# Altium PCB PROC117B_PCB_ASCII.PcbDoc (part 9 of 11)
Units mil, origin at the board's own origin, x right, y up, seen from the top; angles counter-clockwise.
Board outline 2480.32 x 3185.25 mil, 8 copper layers (Top Layer, L2_GND1, L3_SIG1, L4_PWR1, L5_PWR2, L6_SIG2, L7_GND2, Bottom Layer), stack 57.4 mil thick; 456 components, 292 nets, 7831 pads, 2905 vias.
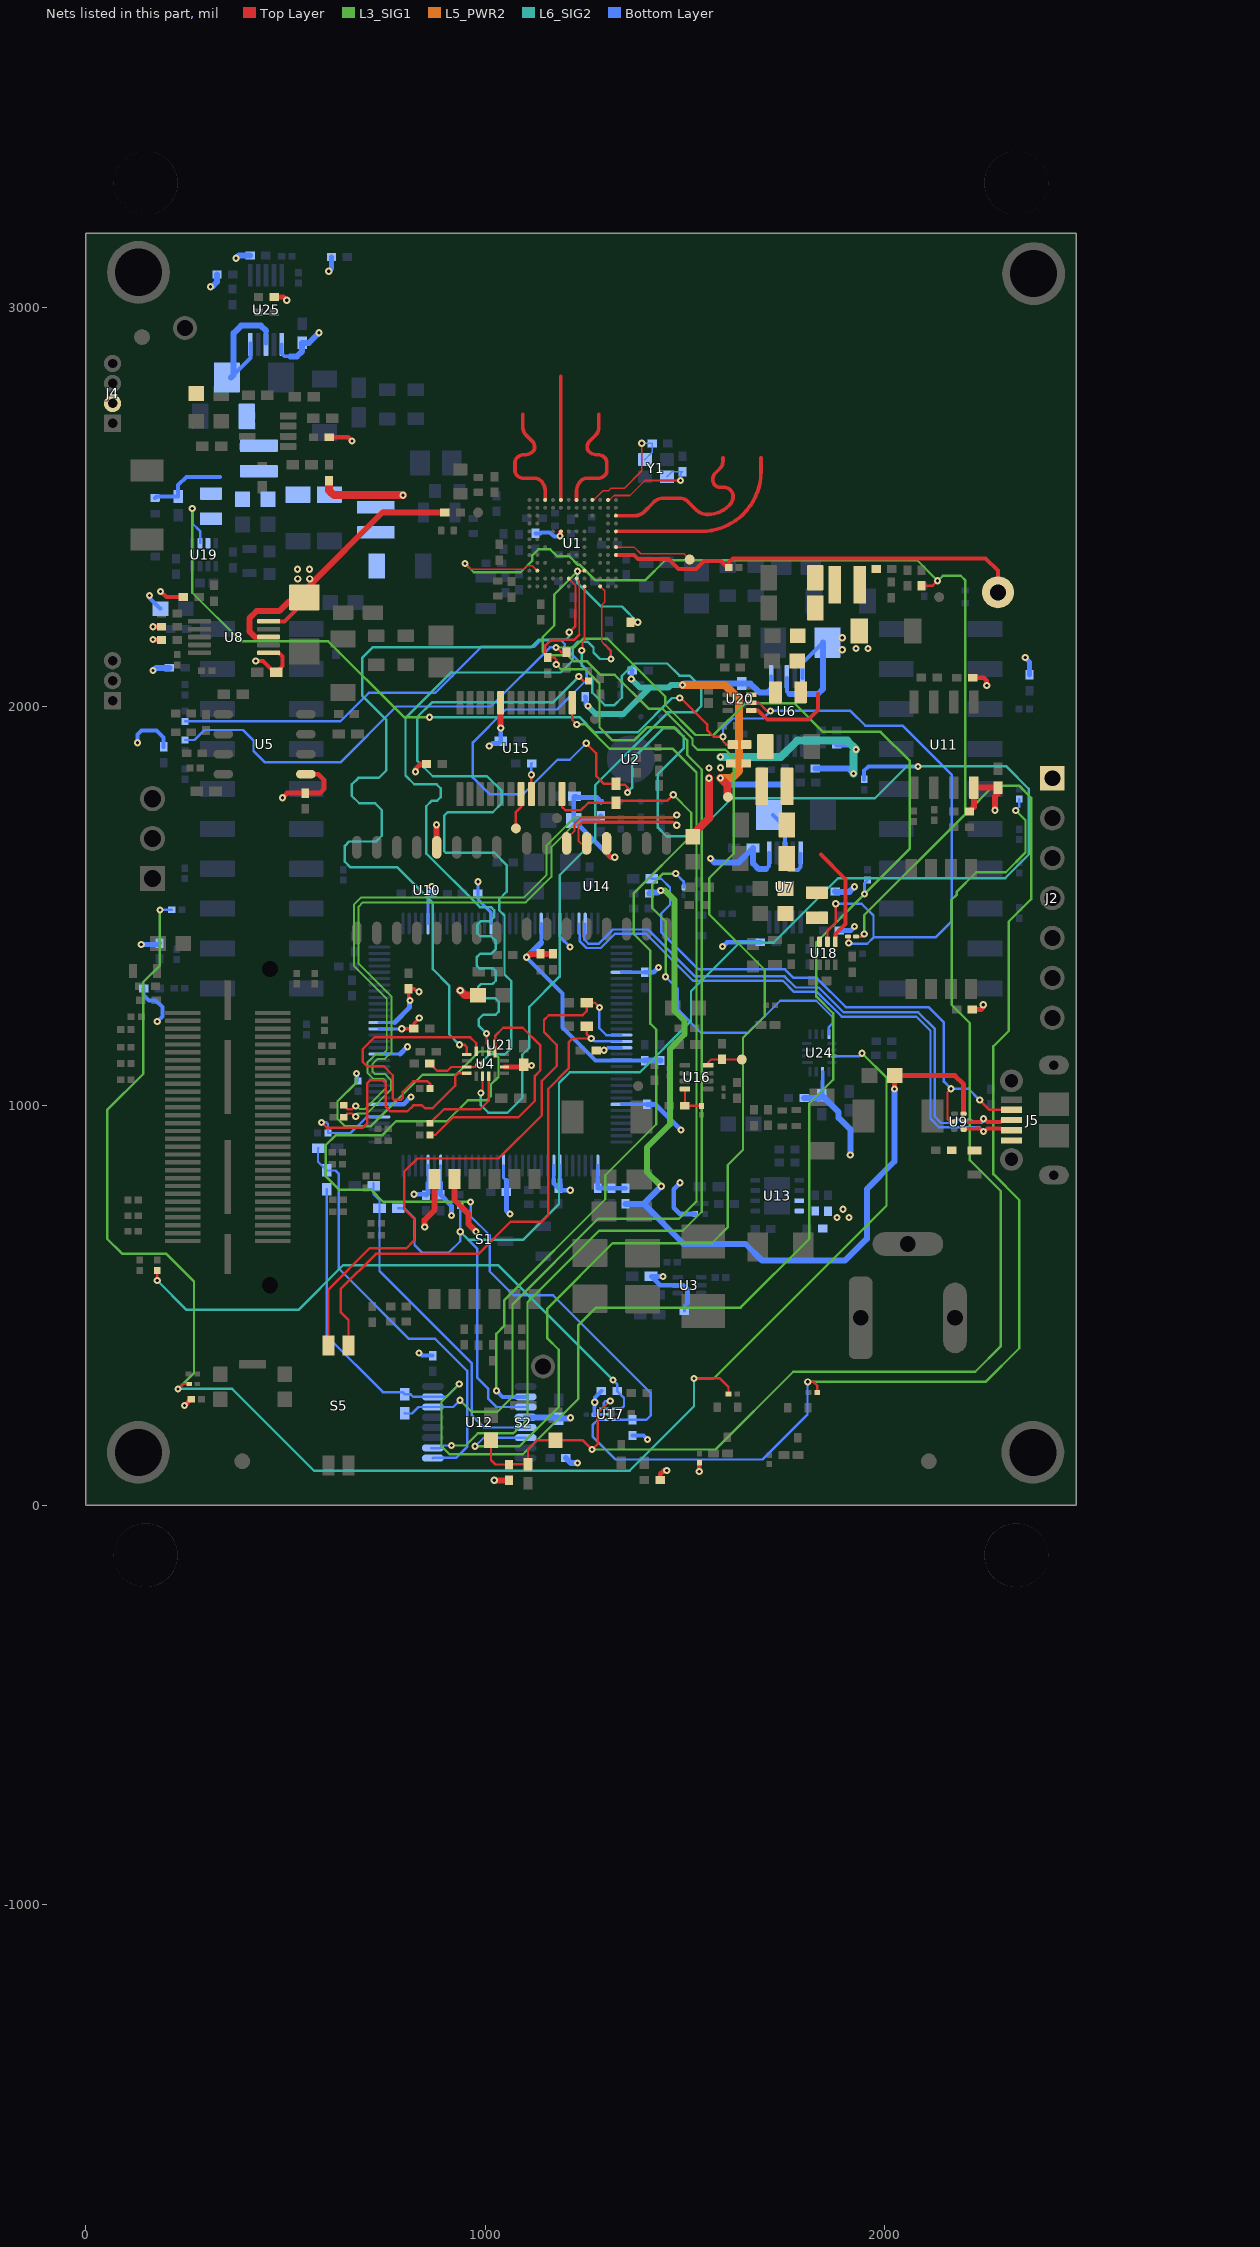
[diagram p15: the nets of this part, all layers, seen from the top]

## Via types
v1: diameter 18, hole 8, Top Layer to Bottom Layer, tented both sides, 2905 vias

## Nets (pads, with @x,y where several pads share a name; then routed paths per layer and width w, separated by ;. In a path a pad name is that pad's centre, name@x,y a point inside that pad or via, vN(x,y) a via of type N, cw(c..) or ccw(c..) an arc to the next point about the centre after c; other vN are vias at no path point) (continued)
RADAR_LVDS_FRCLKM: R220.2 U14.5 | length 1960.4
  Top Layer w5.2: R220.2@645.83,971.22 646.62,971.22 652.29,976.89 652.29,978.08 655.33,981.12 666.38,981.12 674.28,973.22 v1(675.83,973.22) ; U14.5@1254.22,1657.18 1239.83,1657.18 1234.32,1662.68 1234.32,1701.84 1243.87,1711.39 1469.39,1711.39 1478.2,1702.58 v1(1479.75,1702.58)
  L3_SIG1 w4.8: v1(675.83,973.22) 675.83,977 679.05,980.22 704.2,980.22 760.48,1036.5 763.99,1040.01 763.99,1065.29 749.75,1079.53 724.78,1079.53 717.58,1086.73 717.58,1104.64 730.6,1117.66 749.15,1117.66 765.65,1134.16 765.65,1273.65 683.17,1356.13 683.17,1498.96 693.76,1509.55 1102.17,1509.55 1165.8,1573.18 1165.8,1647.32 1228.05,1709.58 1476.23,1709.58 1479.75,1706.06 v1(1479.75,1702.58)
RADAR_LVDS_FRCLKP: R219.2 U14.6 | length 1966.3
  Top Layer w5.2: R219.2@645.83,1001.22 646.62,1001.22 652.29,995.55 652.29,994.37 655.33,991.32 666.38,991.32 674.28,999.22 v1(675.83,999.22) ; U14.6@1204.22,1657.18 1204.22,1669.04 1224.12,1688.94 1224.12,1706.07 1239.64,1721.59 1471.21,1721.59 1478.2,1728.58 v1(1479.75,1728.58)
  L3_SIG1 w4.8: v1(675.83,999.22) 678.3,999.22 685.3,992.22 699.23,992.22 751.99,1044.98 751.99,1060.32 744.78,1067.53 719.81,1067.53 705.58,1081.75 705.58,1109.61 725.63,1129.66 744.18,1129.66 753.65,1139.13 753.65,1268.68 671.17,1351.16 671.17,1503.93 688.79,1521.55 1097.2,1521.55 1153.8,1578.15 1153.8,1652.3 1223.08,1721.58 1470.28,1721.58 1477.28,1728.58 v1(1479.75,1728.58) v1@1482.22,1728.58
RADAR_NRST: R20.1 R171.1 R176.1 U1.L10 U17.4 | length 5647.1
  Top Layer w4: v1(949.71,2358.2) 964.56,2343.34 1061.19,2343.34 1096.59,2343.46 1105.56,2352.43 1118.35,2352.43 U1.L10@1130.68,2340.09
  Top Layer w6: v1(1808.03,308.72) 1822.18,308.72 1832.03,298.88 R171.1@1832.03,281.86 ; R176.1@1928.78,1423.59 1942.92,1423.59 1949.21,1429.88 v1(1949.27,1429.88) ; R20.1@2092.59,2302.27 2120.49,2302.27 v1(2133.25,2315.03)
  L3_SIG1 w6: v1(949.71,2358.2) 949.71,2357.89 971.5,2336.09 1045.03,2336.09 1089.09,2336.09 1118.25,2365.26 1118.25,2378.67 1133,2393.41 1162.99,2393.41 1179.98,2376.42 1210.58,2376.42 1232.3,2354.7 1237.61,2354.7 1276.52,2315.79 1400.78,2315.79 1451.15,2366.15 2082.13,2366.15 v1(2133.25,2315.03) 2134.12,2315.03 2146.41,2327.32 2190.94,2327.32 2202.8,2315.46 2202.8,1731.03 ; v1(1808.03,308.72) 2253.43,308.72 2337.65,392.95 2337.65,764.06 2272.88,828.83 2272.88,1149.03 2311.25,1187.4 2311.25,1461.23 2367.33,1517.31 2367.33,1771.56 2337.03,1801.86 2273.63,1801.86 2202.8,1731.03 ; v1(1949.27,1429.88) 1949.27,1477.5 2202.8,1731.03
  Bottom Layer w6: U17.4@1297.06,213.79 1282,213.79 1269.92,201.71 1269.92,170.6 1326.34,114.19 1694.32,114.19 1807.37,227.23 1807.37,308.07 v1(1808.03,308.72)
RADAR_NRST_1: R63.1 R123.1 U17.1 | length 1461.9
  Top Layer w6: R63.1@178.77,587.81 178.77,562.52 v1(178.88,562.41)
  L6_SIG2 w6: v1(178.88,562.41) 252.48,488.8 532.5,488.8 644.67,600.98 1032.64,600.98 v1(1320.06,313.56)
  Bottom Layer w6: v1(1320.06,313.56) 1330.48,303.14 R123.1@1330.48,286.13 1347.92,268.68 1347.92,247.86 1341.68,241.62 1328.98,241.62 U17.1@1328.64,241.27
RADAR_NRST_2: C53.1 R144.2 R165.1 S2.3 S2.4 U17.6 | length 3223.4
  Top Layer w6: S2.3@1014.65,162.25 1014.65,113.17 1026.18,101.64 R165.1@1059.52,101.64 1060.06,102.18 C53.1@1107.4,102.18 1107.4,140.54 1129.11,162.25 S2.4@1176.07,162.25 1245.19,162.25 v1(1268.03,139.41) 1281.95,153.32 1281.95,230.43 1312,260.48 v1(1313.49,260.48)
  L3_SIG1 w6: v1(1268.03,139.41) 1576.81,139.41 1771.53,334.13 2227.54,334.13 2291.74,398.33 2291.74,785.89 2213.63,863.99 2213.63,1207.19 2168.48,1252.34 2168.48,1516.08 2180.67,1528.26 2180.67,1535.44 2230.07,1584.83 2303.72,1584.83 2353.12,1634.23 2353.12,1715.1 2328.74,1739.48 v1(2328.74,1739.75)
  Bottom Layer w6: U17.6@1297.14,241.27 1297.14,256.35 1301.27,260.48 v1(1313.49,260.48) ; v1(2328.74,1739.75) 2337.72,1748.72 R144.2@2337.72,1768.04
RADAR_OSC_CLKOUT: TP5.1 U1.A7 | length 197.5
  Top Layer w4: U1.A7@1327.53,2399.14 1372.89,2399.14 1389.63,2382.41 1497.99,2382.41 TP5.1@1512.19,2368.21
RADAR_VBGAP: C6.1 U1.H5 | length 79.3
  Top Layer w10: v1@1187.9,2426.87 1187.98,2426.96 1187.98,2436.9 U1.H5@1189.59,2438.51
  Bottom Layer w10: C6.1@1125.93,2433.58 1138.28,2433.58 1140.85,2436.16 1161.58,2436.16 1169.56,2428.17 1170.97,2428.17 1173.85,2425.3 1185.21,2425.3 v1@1186.74,2423.77
  other v1: 1187.35,2426.87
REG_1V2: C61.2 L5.2 R86.2 R193.1 U8.8 U8.10 | length 795.3
  Top Layer w10: U8.8@454.65,2173.58 424.5,2173.58 424.61,2173.69 454.76,2173.69 U8.8@454.84,2173.77 ; U8.10@454.84,2213.14 497.82,2213.14 R193.1@547.27,2262.59
  Top Layer w15: 424.5,2173.58 409.76,2188.31 409.76,2220.8 427.63,2238.67 484.43,2238.67 508.35,2262.59 R193.1@547.27,2262.59 ; R193.1@560.88,2303.88 743.17,2486.17 R86.2@899.02,2486.17
  other v1: 530.64,2319.62 560.64,2319.62 530.18,2343.72 560.18,2343.72
REG_1V8: C68.2 L6.2 R67.2 R192.1 U6.8 U6.10 | length 358.6
  Bottom Layer w10: U6.8@1755.6,2071.89 1755.68,2071.82 1755.68,2037.44 1761.92,2031.21 ; U6.10@1794.9,2071.82 1794.97,2071.9 1794.97,2108.35 R192.1@1846.57,2159.94
  Bottom Layer w15: 1761.92,2031.21 1833.56,2031.21 1846.57,2044.22 R192.1@1846.57,2159.94
  other v1: 1894.25,2142.27 1928.89,2145.49 1958.89,2145.49 1894.25,2172.27
REG_3V3: C54.2 L4.2 L11.1 R175.2
REG_MODE_SELECT: R173.2 U24.8 | length 962.2
  L3_SIG1 w6: v1(1451.98,1323.34) 1451.98,1462.11 1418.4,1495.69 1418.4,1554.61 1445.3,1581.52 v1(1477.34,1581.52)
  Bottom Layer w6: v1(1451.98,1323.34) 1482.75,1292.57 1482.75,1240.95 1540.68,1183.02 1658.67,1183.02 1738.92,1263.26 1829.29,1263.26 1870.7,1221.85 1870.7,1206.94 1860.85,1197.09 U24.8@1860.85,1179.47 ; v1(1477.34,1581.52) 1496.97,1561.88 R173.2@1496.97,1546.64
REG_OUT_1V2: C100.1 C119.1 C120.1 C121.2 C122.2 L1.1 L5.1 L14.2 R119.2 | length 200.9
  Bottom Layer w10: R119.2@173.4,2521.99 177.34,2525.92 C100.1@231.43,2525.92 231.43,2554.55 251.9,2575.02 335.59,2575.02
REG_OUT_1V8: C128.1 C129.1 C130.2 C131.2 L6.1 L15.2 U20.5 | length 227.8
  Top Layer w10: U20.5@1666.44,1989.74 1683.73,1989.74 1706.56,1966.91 1809.81,1966.91 1833.91,1991.01 1833.91,2031.87
REG_OUT_3V3: C70.1 C71.1 C87.2 C107.2 L4.1 L13.2 U18.5 | length 253.4
  Top Layer w10: 1840.73,1628.74 1902.12,1567.35 1902.12,1454.84 1877,1429.72 U18.5@1877,1411.2
REG_PG: R175.1 R176.2 U18.6 U19.6 U20.6 | length 3569.1
  Top Layer w6: v1@1487.69,2021.63 1489.74,2021.63 1555.82,1955.55 1555.82,1941.03 1572.49,1924.36 v1(1595.63,1924.36) 1595.63,1912.72 1603.74,1904.61 R175.1@1620.22,1904.61 ; U20.6@1666.44,2009.43 1685.54,2009.43 1706.06,1988.9 v1(1714.73,1988.9) ; U18.6@1857.32,1411.2 1857.32,1438.92 1878.16,1459.76 v1(1878.16,1506.05) ; R176.2@1908.74,1423.58 1910.84,1421.47 1910.84,1408.22 v1(1910.7,1408.08)
  L3_SIG1 w6: v1(266.77,2496.14) 266.77,2284.85 388.26,2163.36 606.96,2163.36 796.83,1973.49 860.11,1973.49 v1(860.36,1973.24)
  L6_SIG2 w6: v1(860.36,1973.24) 1236.48,1973.24 1274.68,1935.04 1382.23,1935.04 1468.4,2021.21 v1(1487.26,2021.21)
  Bottom Layer w6: v1(266.77,2496.14) 266.77,2458.77 286.16,2439.39 U19.6@286.16,2409.31 ; v1(1595.63,1924.36) 1595.63,1945.68 1619.86,1969.92 1695.76,1969.92 v1(1714.73,1988.9) 1915.09,1988.9 1951.8,1952.2 2044.96,1952.2 2168.78,1828.37 2168.78,1462.54 2127.95,1421.71 1972.94,1421.71 1972.59,1421.37 ; v1@1878.19,1506.08 1942.75,1506.08 1972.59,1476.23 1972.59,1421.37 ; v1(1910.7,1408.08) 1912.91,1405.86 1957.09,1405.86 1972.59,1421.37
REG_RF_1V2: C79.2 L1.2 R134.1 U25.8 U25.10 | length 336
  Bottom Layer w10: R134.1@370.06,2830.09 412.12,2872.14 U25.10@412.12,2909.57 ; U25.8@451.49,2909.57 451.49,2940.73
  Bottom Layer w15: R134.1@363.96,2823.99 370.06,2830.09 370.06,2934.69 389.09,2953.72 438.51,2953.72 451.49,2940.73
RTC_CLKIN: TP3.1 U15.19 | length 91.5
  Top Layer w6: TP3.1@1077.13,1694.73 1077.13,1735.48 1090.23,1748.57 U15.19@1090.23,1780.76
RX1: U1.K1 | length 309.6
  Top Layer w9.3: 1094.55,2731.78 1094.55,2699.27 ccw(c1121.99,2699.27) 1102.59,2679.86 1119.96,2662.49 cw(c1101.47,2650.16) 1123.6,2648.08 ; 1097.57,2630.35 ccw(c1097.57,2605.68) 1080.13,2623.12 ccw(c1093.52,2609.73) 1074.58,2609.73 1074.58,2591.11 ccw(c1092.01,2591.11) 1079.68,2578.78 ccw(c1097.13,2596.23) 1097.13,2571.56 1124.48,2571.56 cw(c1124.48,2550.15) 1139.62,2565.29 cw(c1113.67,2539.34) 1150.37,2539.34 U1.K1@1150.37,2517.25 ; 1097.57,2630.4 ccw(c1099.24,2659.57) 1119.9,2638.91 ccw(c1110.74,2648.07) 1123.69,2648.07
RX2: U1.H1 | length 309.7
  Top Layer w9.3: U1.H1@1189.74,2517.25 1189.74,2826.97
RX3: U1.F1 | length 309.6
  Top Layer w9.3: U1.F1@1229.11,2517.25 1229.11,2539.34 cw(c1265.8,2539.34) 1239.85,2565.29 cw(c1254.99,2550.15) 1254.99,2571.56 1282.35,2571.56 ccw(c1282.35,2596.23) 1299.79,2578.79 ccw(c1287.46,2591.11) 1304.9,2591.11 1304.9,2609.73 ccw(c1285.95,2609.73) 1299.35,2623.12 ccw(c1281.91,2605.68) 1281.91,2630.35 ; 1255.78,2648.07 ccw(c1268.73,2648.07) 1259.57,2638.91 ccw(c1280.23,2659.57) 1281.9,2630.4 ; 1255.88,2648.08 cw(c1278,2650.16) 1259.51,2662.49 1276.88,2679.86 ccw(c1257.48,2699.27) 1284.92,2699.27 1284.92,2731.78
SW1: L13.1 U18.7
SW2: L14.1 U19.7
SW3: L15.1 U20.7
SW_PR1: R102.1 R120.2 U16.4 | length 84.3
  Top Layer w5.2: U16.4@1500.5,1042.21 1500.5,1000.6 R102.1@1500.04,1000.15 1541.34,1000.15 R120.2@1541.9,999.59
SW_ST: R76.1 TP8.1 U16.8 | length 94.4
  Top Layer w5: U16.8@1558.76,1101.26 1558.76,1108.47 1566.34,1116.04 R76.1@1592.79,1116.04 TP8.1@1642.74,1116.04
TS3A_ENn: R91.1 U15.20 | length 76.9
  Top Layer w6: v1(1115.77,1829) v1(1115.77,1829) U15.20@1115.82,1780.76
  Bottom Layer w6: v1(1115.77,1829) 1115.77,1856.74 R91.1@1116.42,1857.39
TX1: U1.A3 | length 482
  Top Layer w9.3: U1.A3@1327.53,2477.88 1375.21,2477.88 ccw(c1375.21,2509.63) 1397.66,2487.18 1420.86,2510.39 cw(c1448.35,2482.9) 1448.35,2521.77 1486.72,2521.77 cw(c1486.72,2491.17) 1508.36,2512.81 1528.82,2492.34 ccw(c1557.09,2520.61) 1557.09,2480.63 ccw(c1557.09,2555.97) 1610.36,2502.7 1612.42,2504.76 ccw(c1591.8,2525.38) 1620.96,2525.38 ccw(c1597.2,2525.38) 1597.2,2549.13 1588.01,2549.13 cw(c1588.01,2566.74) 1570.4,2566.74 1570.4,2570.36 cw(c1589.97,2570.36) 1576.13,2584.2 1588.6,2596.67 ccw(c1571.43,2613.83) 1595.71,2613.83 1595.71,2622.33
TX2: U1.A5 | length 482.9
  Top Layer w9.3: U1.A5@1327.53,2438.51 1541.16,2438.51 ccw(c1541.16,2588.27) 1690.92,2588.27 1690.92,2622.33
USB_5V: C86.2 J5.1 L9.1
USER_LED_SW_GPIO_0: R66.1 R149.1 R214.2 U24.11 | length 4261.1
  Top Layer w6: v1(231.16,291.03) v1(231.16,291.03) 243.35,303.27 R214.2@259.28,303.27 ; v1(1523.21,317.26) 1587.96,317.26 1609.41,295.82 R66.1@1609.41,278.61
  L3_SIG1 w6: v1(185.7,1490.43) 185.7,1351.38 143.96,1309.65 143.96,1079.97 53.37,989.37 53.37,667.14 90.73,629.78 201.24,629.78 271.04,559.98 271.04,330.9 v1(231.16,291.03) ; v1(1523.21,317.26) 1572.46,317.26 2005.1,749.9 2005.1,1070.82 v1(1944.15,1131.77)
  L6_SIG2 w6: v1(231.16,291.03) 366.82,291.03 571.56,86.29 1361.87,86.29 1523.21,247.63 v1(1523.21,317.26)
  Bottom Layer w6: v1(185.7,1490.43) 186.19,1490.92 214.53,1490.92 R149.1@215.02,1491.41 ; U24.11@1868.72,1124.36 1937.19,1124.36 1944.15,1131.32 v1(1944.15,1131.77)
VBAT: J4.2 R32.1 | length 0.1
  Top Layer w25: R32.1@276.36,2783.93 R32.1@276.44,2784.01
VBUS_1_DETECT: C118.2 R236.1 R239.2 U21.1 | length 126.6
  Bottom Layer w6: U21.1@1282.09,849.95 1282.24,850.1 U21.1@1282.31,850.16
  Bottom Layer w8: 1281.97,815.69 1282.24,815.96 U21.1@1282.24,850.1
  Bottom Layer w12: 1281.97,815.69 1281.97,793.75 R239.2@1282.09,793.62 C118.2@1316.92,793.62 R236.1@1351.75,793.62
VCC_3V3: C2.1 C34.1 C35.2 C36.1 C38.2 C40.1 C41.1 C52.2 C57.1 C58.1 C59.1 C65.1 C91.1 C133.1 J2.1 L11.2 R2.2 R5.2 R7.2 R8.2 R14.2 R17.2 R22.2 R27.2 R28.1 R44.2 R49.2 R50.1 R54.2 R70.2 R90.1 R94.1 R95.2 R96.2 R97.2 R98.2 R99.2 R104.2 R105.2 R106.2 R107.2 R112.1 R115.1 R123.2 R129.1 R130.1 R132.2 R135.2 R136.2 R138.2 R142.1 R157.2 R161.2 R165.2 R172.2 R198.2 R200.1 R213.2 S1.11 S1.12 TP9.1 U2.8 U3.5 U4.14 U5.5 U6.6 U7.6 U7.8 U7.10 U8.6 U10.4 U11.8 U12.12 U14.4 U15.8 U17.5 U24.14 U25.6 | length 6461.4
  Top Layer w8: U8.6@454.84,2134.4 455.02,2134.23 U8.6@483.65,2134.23
  Top Layer w9.84: R28.1@1536.37,106.29 R28.1@1536.57,106.49
  Top Layer w10: v1(187.33,2288.25) 201.54,2274.05 R107.2@244.36,2274.05 ; v1(425.65,2114.11) 444.27,2114.11 472.79,2085.59 C59.1@476.72,2085.59 492.54,2101.38 492.54,2125.34 U8.6@483.65,2134.23
  Top Layer w12: v1(168.15,2167.46) 169.38,2166.23 189.37,2166.23 R115.1@189.51,2166.36 ; v1(168.15,2199.46) 168.24,2199.55 189.42,2199.55 R106.2@189.51,2199.63 ; v1(247.47,249.15) 263.22,264.9 R213.2@264,264.9 ; R135.2@471.89,3025.66 471.98,3025.75 494.95,3025.75 503.16,3017.54 v1(503.16,3017.39) ; v1(492.88,1771.47) 492.88,1771.93 504.02,1783.07 C38.2@549.71,1783.07 586.12,1783.07 596.85,1793.8 596.85,1815.83 582.23,1830.45 U5.5@551.08,1830.45 ; R17.2@609.61,2674.25 656.86,2674.25 v1(666.5,2664.61) ; v1(825.54,1836.49) 825.54,1843.14 838.22,1855.82 R90.1@853.25,1855.82 ; U4.14@1048.51,1097.14 1091.46,1097.14 C40.1@1096.63,1102.31 1097.37,1101.56 1115.3,1101.56 v1(1116.05,1100.81) ; U14.4@1304.22,1657.18 1304.22,1632.61 1314.53,1622.31 v1(1324.73,1622.31) ; R172.2@1438.42,62.98 1438.42,77.97 1447.11,86.66 v1(1454.85,86.66) ; v1(1536.37,84.58) R28.1@1536.37,106.29 ; R70.2@2220.35,1241.02 2242.22,1241.02 2247.53,1246.33 v1(2247.53,1253.08) ; R161.2@2220.61,2071.84 2248.94,2071.84 2256.43,2064.35 v1(2256.43,2052.7)
  Top Layer w15: v1(848.69,696.45) 848.69,713.94 873.28,738.53 S1.12@873.28,816.28 ; v1(878.1,1704) 878.57,1703.54 878.57,1647.65 U10.4@879.03,1647.18 ; S1.11@923.28,816.28 923.28,764.05 958.87,728.46 958.87,703.73 976.81,685.78 v1(976.81,684.83) ; v1(1022.76,62.31) 1022.8,62.27 R165.2@1059.52,62.27 ; v1(1039.05,1946.1) U15.8@1039.05,2009.1 ; R157.2@2213.07,1737.31 2223.96,1748.2 U11.8@2223.96,1796.68 C65.1@2284.36,1796.63 C65.1@2284.36,1796.63 2284.36,1782.32 2276.59,1774.55 v1(2276.59,1740.15)
  Top Layer w20: R22.2@609.31,2565.79 609.31,2541.15 621.34,2529.12 v1(794.72,2529.12) ; v1(937.57,1288.59) 949.3,1276.86 R129.1@982.21,1276.86 ; R130.1@1519.94,1674.02 1519.94,1679.64 1559.21,1718.92 ; 1560.5,1718.92 v1(1560.5,1820.44) ; v1(1589.6,1820.95) 1607.17,1803.38 1607.17,1774 TP9.1@1608.13,1773.05
  L5_PWR2 w20: v1(1494.12,2053.57) 1600.45,2053.57 1635.63,2018.39 1635.63,1838.4 1618.17,1820.95 v1(1589.6,1820.95)
  L6_SIG2 w15: v1(1257.49,2001.11) 1277.38,1981.23 1346.46,1981.23 1346.46,1981.7 1411.83,2047.08 ; v1(1366.13,2068.74) 1387.8,2047.08 1411.83,2047.08 ; v1(1494.12,2053.57) 1465.16,2053.57 1458.67,2047.08 1411.83,2047.08
  L6_SIG2 w20: v1(1589.32,1873.2) 1740.34,1873.2 1781.45,1914.32 1907,1914.32 v1(1928.83,1892.48) 1922.66,1886.31 v1(1922.66,1832.25)
  Bottom Layer w6: C52.2@1273.77,226.49 1283.4,226.49 1284.06,227.14 1296.79,227.14 U17.5@1297.14,227.49
  Bottom Layer w8: R54.2@1499.14,486.5 1499.14,498.84 1504.84,504.54
  Bottom Layer w9: U25.6@490.86,2906.62 490.86,2883.98 498.24,2876.59 512.02,2876.59 ; C36.1@1415.42,573.31 C36.1@1415.88,572.85 ; v1@1444.86,572.85 v1(1445.32,572.4) ; C2.1@1843.46,1025.96 C2.1@1845.1,1027.6 ; 1845.1,1061.36 U24.14@1845.1,1084.99
  Bottom Layer w10: v1(129.66,1909) 129.66,1929.89 139.93,1940.16 177.41,1940.16 195.06,1922.5 R96.2@195.06,1898.73 ; R98.2@145.13,1294.02 145.13,1277.11 158.15,1264.08 175.07,1264.08 192.03,1247.12 192.03,1224.03 v1(178.88,1210.89) ; v1(159.16,2277.84) 159.16,2271.7 186.06,2244.81 R132.2@187.04,2244.81 ; v1(834.59,381.3) 841.35,374.53 R8.2@868.82,374.53 ; C52.2@1273.77,226.49 1273.77,256.58 v1(1274.69,257.5) 1274.69,269.71 R123.2@1291.11,286.13 ; R138.2@1369.02,174.4 1396.65,174.4 v1(1406.6,164.45) ; 1703.25,1592.54 1711.42,1600.71 U7.6@1711.42,1633.41 ; 1716.23,2043.31 U6.6@1716.23,2074.85 ; R200.1@1721.21,1728.34 1750.8,1698.75 1750.8,1600.2 1760.79,1590.2 1782.95,1590.2 1790.27,1597.52 1790.27,1630.36 U7.10@1790.17,1630.46 ; C2.1@1845.1,1027.6 1845.1,1061.36
  Bottom Layer w12: v1(139.06,1403.89) 181.3,1403.89 R97.2@184.93,1407.51 ; v1(608.46,3089.73) 615.31,3096.58 R5.2@615.31,3125.49 ; v1(1010.17,1901.05) 1011.79,1901.05 1017.95,1907.2 1033.36,1907.2 C91.1@1039.18,1913.02 1039.11,1913.08 1039.11,1946.03 v1(1039.05,1946.1) ; R50.1@1250.75,2024.39 1252.11,2023.02 1252.11,2006.49 v1(1257.49,2001.11) ; R49.2@1290.12,1726.38 1278.42,1714.68 C35.2@1221.78,1714.68 ; U2.8@1290.12,1761.89 1279.99,1772.02 1231.11,1772.02 1227.77,1775.36 C34.1@1223.83,1775.36 1221.78,1773.31 C35.2@1221.78,1714.68 ; v1(1324.73,1622.31) 1314.14,1622.31 C35.2@1221.78,1714.68 ; v1(1366.13,2068.74) 1367.28,2069.89 1367.28,2089.04 R44.2@1368.67,2090.43 ; v1@1444.86,572.85 1415.88,572.85 1438.1,550.63 U3.5@1482.65,550.63 1482.74,550.53 1496.57,550.53 1506.84,540.26 1506.84,506.54 1504.84,504.54 ; v1(1487.9,807.26) 1486.66,806.01 1486.66,805.26 1472.45,791.06 1472.45,745.21 1488.79,728.87 R198.2@1526.2,728.87 ; v1(1594.8,1398.59) 1605.94,1409.73 R104.2@1689.34,1409.73 ; R105.2@1886.82,1439.18 1916.04,1439.18 1923.28,1446.42 1923.28,1447.09 v1(1925.27,1449.08) ; v1(2352.62,2122.49) 2362.98,2112.14 R99.2@2362.98,2078.99
  Bottom Layer w15: v1(168.57,2090.4) 169.38,2090.4 175.87,2096.89 R95.2@209.18,2096.89 ; v1(312.45,3051.13) 316.4,3051.13 328.5,3063.24 R136.2@328.5,3081.58 ; v1(376.4,3122.23) 383.13,3128.96 R142.1@411.75,3128.96 ; 512.02,2876.59 528.84,2876.59 541.6,2889.35 C133.1@541.6,2910.79 558.84,2910.79 v1(584.03,2935.98) ; U12.12@1101.47,220.05 1181.17,220.05 C41.1@1184.63,216.58 1198.94,216.58 1199.13,216.77 1211.81,216.77 v1(1213.72,218.68) ; R7.2@1202.21,118.04 1215.08,105.18 v1(1231.46,105.18) ; v1@1494.34,2053.35 1494.71,2053.35 1498.74,2057.39 C57.1@1642.45,2057.39 ; v1(1564.27,1619.59) 1574.96,1608.9 1634.02,1608.9 C58.1@1670.75,1645.63 1670.75,1607.28 1685.5,1592.54 1703.25,1592.54 ; v1(1589.6,1820.95) 1605.99,1804.56 R94.1@1751.5,1804.56 ; C57.1@1642.68,2057.61 1664.25,2057.61 1686.59,2035.27 1708.19,2035.27 1716.23,2043.31 ; R27.2@1799.03,1019.16 1839.15,1019.16 1843.46,1023.47 C2.1@1843.46,1025.96 1885.49,983.93 1885.49,969.91 1914.52,940.88 v1(1914.52,876.78) ; R2.2@1827.17,1844.36 1827.24,1844.43 1910.48,1844.43 v1(1922.66,1832.25) ; R112.1@1876.47,1536.55 1877.26,1535.76 1912.32,1535.76 v1(1925.04,1548.48) v1@1923.85,1549.67 ; R14.2@1880.65,1904.72 1916.59,1904.72 v1(1928.83,1892.48)
  other v1: 1560.55,1846.11 1589.37,1846.63
VCC_XDS_3V3: C105.2 C106.2 C108.1 C113.2 C114.1 C115.1 C116.2 C117.2 R10.2 R195.2 R196.2 R202.1 R231.2 R233.2 U13.3 U13.4 U21.7 U21.8 U21.16 U21.26 U21.28 U21.39 U21.47 U21.51 U21.52 U21.69 U21.79 U21.90 U21.101 U21.113 U21.122 | length 1598.6
  Top Layer w8: v1(791.25,1192.81) 821.21,1192.81 R195.2@821.56,1193.16 821.56,1205.5 834.99,1218.93 v1(834.99,1219.67) ; v1(811.62,1263.68) 808.57,1266.73 808.57,1292.88 R196.2@808.39,1293.06 822.92,1293.06 830.34,1285.63 v1(834.78,1285.63) ; C115.1@1277.83,1138.62 1278.19,1138.98 1297.47,1138.98 v1(1297.82,1139.33)
  Bottom Layer w8: U21.39@735.06,1003.71 765.55,1003.71 ; U21.47@735.06,1129.69 787.01,1129.69 ; U21.51@735.06,1192.68 791.12,1192.68 v1(791.25,1192.81) ; U21.52@735.06,1208.43 759.19,1208.43 759.29,1208.33 773.07,1208.33 ; v1@810.95,1263.02 v1(811.62,1263.68) ; 857.11,807.39 U21.28@857.11,850.16 ; U21.69@857.11,1456.46 857.11,1521.41 866.29,1530.6 R231.2@866.37,1530.6 866.56,1530.78 v1(866.54,1549.28) ; 888.61,807.77 U21.26@888.61,850.16 ; v1(981.92,1560.96) R202.1@981.92,1531.94 981.92,1517.75 1014.59,1485.08 U21.79@1014.59,1456.46 ; U21.16@1046.09,850.16 1046.09,819.78 1053.23,812.63 ; 1172.07,816.29 U21.8@1172.07,850.16 ; 1187.82,816.09 U21.7@1187.82,850.16 ; U21.90@1187.82,1456.46 1187.82,1422.53 v1(1212.52,1397.83) ; v1(1297.82,1139.33) 1300.53,1139.33 1306.57,1145.38 U21.113@1341.36,1145.38 ; U21.122@1341.36,1003.71 1404.62,1003.71 C106.2@1404.89,1003.44 ; U21.101@1341.36,1334.41 1341.47,1334.52 C108.1@1399.6,1334.52
  Bottom Layer w12: 765.55,1003.71 795.79,1003.71 814.31,1022.23 v1(814.64,1022.23) ; 773.07,1208.33 810.95,1246.22 v1@810.95,1263.02 ; 787.01,1129.69 v1(805.33,1148.02) ; v1(822.24,778.52) 849.59,778.52 C114.1@852.08,776.02 857.11,781.05 857.11,807.39 ; 888.61,807.77 888.61,777.03 C113.2@888.65,776.98 915.7,749.94 v1(915.7,725.31) ; 1053.23,812.63 C116.2@1053.23,784.51 1053.23,737.82 v1(1062.06,728.99) ; 1172.07,816.29 1172.07,805.79 R233.2@1183.89,793.97 ; 1187.82,816.09 1187.82,797.9 R233.2@1183.89,793.97 ; v1(1213.25,788.5) 1189.37,788.5 R233.2@1183.89,793.97 ; C108.1@1399.6,1334.52 1422.37,1334.52 v1(1433.98,1346.13) ; C106.2@1404.89,1003.44 1426.39,1003.44 v1(1490.79,939.03)
  other v1: 1881.49,720.05 1911.49,720.05 1896.44,740.83
VDDC_1: C124.2 C125.2 C126.2 C127.1 U21.87 U21.115 | length 662.3
  Top Layer w15: v1(1103.81,1371.91) 1112.18,1380.28 C125.2@1138.59,1380.28 1170.05,1380.28 C124.2@1170.32,1380.54
  Bottom Layer w8: 1140.58,1408.67 U21.87@1140.58,1456.46
  Bottom Layer w10: v1(1103.81,1371.91) 1194.31,1281.41 1194.31,1196.19 1276.56,1113.94 U21.115@1341.36,1113.94 1398.8,1113.94 C127.1@1399.6,1113.13
  Bottom Layer w15: v1(1103.81,1371.91) 1140.58,1408.67 ; C127.1@1399.6,1113.13 1399.78,1113.31 1438.81,1113.31 C126.2@1438.99,1113.49
VPP_1P7: C31.2 TP10.1 U1.A8 | length 1074.6
  Top Layer w10: U1.A8@1327.53,2379.46 1372.42,2379.46 1382.4,2369.48 1459,2369.48 1483.94,2344.54 1527.71,2344.54 1547.75,2364.58 1590.15,2364.58 C31.2@1609.82,2344.91 ; C31.2@1609.89,2344.83 C31.2@1609.82,2344.91 ; TP10.1@2284.36,2285.93 2284.36,2340.03 2253.53,2370.87 1620.2,2370.87 1609.82,2360.5 C31.2@1609.82,2344.91
XDS_DCA_LP_RS232_RX: R74.1 U1.F11 U12.2 | length 3091.5
  Top Layer w4: U1.F11@1229.11,2320.4 1236.06,2313.45 1236.06,2179.85
  Top Layer w6: v1(1178.05,2105.17) 1178.05,2117.18 1172.58,2122.65 R74.1@1156.68,2122.65 1150.9,2128.43 1150.9,2152.95 1164.73,2166.78 1222.99,2166.78 1236.06,2179.85
  L3_SIG1 w6: v1(916.13,149.19) 951.34,149.19 982.03,179.89 1071,179.89 1106.25,215.13 1106.25,507.96 1285.29,687.01 1495,687.01 1542.5,734.5 1542.5,1841.99 1506.04,1878.44 1506.04,1914.95 1473.27,1947.73 1405.45,1947.73 1372.87,1915.15 1319.1,1915.15 1286.38,1947.87 1286.38,2057.37 1250.56,2093.19 1189.65,2093.19 1178.05,2104.78 v1(1178.05,2105.17)
  Bottom Layer w6: U12.2@865.5,142.54 U12.2@886.33,142.54 ; U12.2@890.01,143.27 895.93,149.19 v1(916.13,149.19)
XDS_DCA_LP_RS232_TX: R73.1 U1.E10 U12.14 | length 3568
  Top Layer w6: v1(1231.19,2338.49) 1231.99,2339.29 1247.99,2339.29 U1.E10@1248.79,2340.09 ; R73.1@1363.83,2210.84 1364.1,2211.12 v1(1382.41,2211.12)
  L3_SIG1 w6: v1(975.04,147.44) 1085.99,147.44 1184.25,245.7 1184.25,388.94 1155.87,417.32 1155.87,492.17 1319.41,655.71 1567.49,655.71 1607.16,695.38 1607.16,851.3 1645.89,890.02 1645.89,1170.23 1700.08,1224.43 1700.08,1340.61 1560.92,1479.77 1560.92,1569.72 1622.29,1631.09 1622.29,1871.38 1601.88,1891.78 1531.83,1891.78 1519.27,1904.35 1519.27,1919.09 1443.69,1994.67 1409.11,1994.67 1324.72,2079.06 1289.23,2079.06 1255.35,2112.95 1221.82,2112.95 1206.82,2127.95 1153.9,2127.95 1144.5,2137.35 1144.5,2174.11 1173.08,2202.69 1173.08,2280.37 v1(1231.19,2338.49)
  L6_SIG2 w6: v1(1231.19,2338.49) 1231.19,2309.64 1290.41,2250.42 1343.11,2250.42 v1(1382.41,2211.12)
  Bottom Layer w6: v1(975.04,147.44) 996.46,168.86 U12.14@1101.47,168.86
XDS_DCA_TCK: U1.C12 U4.2 | length 2121.8
  Top Layer w4: U1.C12@1288.16,2300.72 1299.25,2289.63 1299.25,2261.44 1291.87,2254.06 1291.87,2162.45 1299.91,2154.42
  Top Layer w6: v1(1003.76,1180.89) 1004.02,1180.63 1004.02,1155.94 1009.14,1150.83 U4.2@1009.14,1136.51 ; 1299.91,2154.42 1315.05,2139.28 v1(1315.05,2118.91)
  L6_SIG2 w6: v1(1003.76,1180.89) 983.77,1200.88 983.77,1216.83 994.97,1228.03 1026.25,1228.03 1034,1235.78 1034,1260.59 1025.6,1268.99 988.47,1268.99 982.3,1275.17 982.3,1297.57 989.79,1305.07 1018.37,1305.07 1026.66,1313.35 1026.66,1337.24 1019.35,1344.56 985.22,1344.56 979.37,1350.41 979.37,1372.83 987.66,1381.12 1015.86,1381.12 1027.12,1392.38 1027.12,1412.35 1014.96,1424.51 987.79,1424.51 979.86,1432.45 979.86,1452.49 989.86,1462.5 1012.7,1462.5 1022.74,1472.54 1022.74,1489.33 1014.59,1497.48 986.84,1497.48 852.66,1631.66 852.66,1750.11 866.94,1764.38 879.98,1764.38 888.72,1773.12 888.72,1794.92 878.47,1805.17 822.42,1805.17 800.52,1827.07 800.52,1971.01 914.67,2085.16 1189.38,2085.16 1219.37,2115.15 1219.37,2149.45 1232.3,2162.38 1256.55,2162.38 1271.29,2147.65 1271.29,2135.29 1287.67,2118.91 v1(1315.05,2118.91)
XDS_DCA_TDI: U1.G11 U4.5 | length 2117.9
  Top Layer w4: U1.G11@1209.42,2320.4 1226.23,2303.59 1226.23,2240.13
  Top Layer w6: v1(936.03,1152.65) 948.63,1152.65 954.03,1147.25 U4.5@954.03,1128.64 ; v1(1210.83,2185.91) 1226.06,2201.14 1226.06,2240.13
  L6_SIG2 w6: v1(936.03,1152.65) 910.1,1178.59 910.1,1301.09 909.82,1301.37 869.11,1342.08 869.11,1508 779.28,1597.84 661.86,1597.84 648.71,1610.98 648.71,1650.97 659.53,1661.79 726.94,1661.79 741.32,1676.17 741.32,1740.63 724.37,1757.58 684.76,1757.58 666.15,1776.18 666.15,1804.89 682.53,1821.27 733.69,1821.27 752.84,1840.42 752.84,1966.39 691.97,2027.25 691.97,2121.48 718.34,2147.84 1115.32,2147.84 1134.82,2167.34 1202.29,2167.34 1210.83,2175.88 v1(1210.83,2185.91)
XDS_DCA_TDO_SOP0: R93.1 R156.2 U4.7 | length 1989.9
  Top Layer w6: R156.2@861.61,1105.72 880,1087.33 905.21,1087.33 915.03,1097.14 U4.7@954.03,1097.14 974.36,1097.14 979.75,1102.53 v1(984.19,1102.53) ; v1(1234.68,2075.19) 1234.68,2075.11 1246.05,2063.74 R93.1@1258.82,2063.74
  L6_SIG2 w6: v1(984.19,1102.53) 1010.7,1129.05 1049.83,1129.05 1065.71,1144.93 1065.71,1311.84 1048.67,1328.88 1048.67,1476.15 1035.36,1489.46 1035.36,1517.34 1053.97,1535.95 1053.97,1603.12 1023.33,1633.75 901.16,1633.75 897.62,1637.29 897.62,1726.75 906.18,1735.31 1019.01,1735.31 1042.08,1758.38 1042.08,1788.04 1004.7,1825.43 869,1825.43 829.6,1864.83 829.6,1972.83 866.91,2010.13 1169.63,2010.13 v1(1234.68,2075.19)
XDS_DCA_TMS: U1.E12 U4.10 | length 2119.2
  Top Layer w4: v1(1242.09,2140.16) 1243.91,2141.98 1243.91,2160.68 1248.79,2165.56 U1.E12@1248.79,2300.72
  Top Layer w6: v1(989.31,1031.68) 989.31,1031.81 993.4,1035.9 U4.10@993.4,1073.52
  L6_SIG2 w6: v1(989.31,1031.68) 989.31,1001.45 1008.19,982.57 1055.7,982.57 1093.07,1019.94 1093.07,1127.66 1110.92,1145.51 1110.92,1247.88 1186.49,1323.45 1186.49,1577.44 1275.87,1666.82 1275.87,1803.43 1457.72,1985.28 1525.59,1985.28 1541.02,2000.71 1541.02,2048.14 1511.97,2077.19 1486.51,2077.19 1456,2107.71 1373.85,2107.71 1342.34,2076.2 1342.34,2021.87 1323.97,2003.49 1299.64,2003.49 1268.75,2034.39 1268.75,2075.18 1242.09,2101.84 v1(1242.09,2140.16)
XDS_NRST: R126.2 R138.1 U17.3 | length 2554.7
  L3_SIG1 w6: v1(677.67,1081.25) 677.67,1058.51 630.38,1011.21 630.38,967.39 648.63,949.13 714.44,949.13 843.17,1077.86 927.26,1077.86 985.49,1136.09 1018.66,1136.09 1033.48,1121.27 1033.48,1072.49 1014.18,1053.19 1014.18,1024.32 1003.54,1013.68 956.47,1013.68 904.04,961.26 776.75,961.26 741.52,926.03 625.42,926.03 600.69,901.31 600.69,823.9 634.49,790.11 714.31,790.11 744.98,759.44 v1(963.7,759.44)
  Bottom Layer w6: v1(677.67,1081.25) 681.65,1077.27 R126.2@681.65,1062.42 ; v1@964.03,759.11 964.03,723.16 1011.46,675.73 1011.46,585.13 1071.21,525.39 1170.3,525.39 1414.81,280.88 1414.81,224.41 1404.17,213.77 R138.1@1369.02,213.77 1328.69,213.77 U17.3@1328.64,213.71
XDS_RS232_RX: R24.2 R188.1 U12.1 | length 1051.2
  Bottom Layer w6: R188.1@581.85,893.62 581.62,893.39 581.62,859.95 R24.2@603.36,838.22 603.68,837.89 625.56,837.89 632.98,830.47 632.98,593.12 809.76,416.35 875.3,416.35 955.02,336.63 955.02,145.98 927.22,118.18 869.68,118.18 U12.1@869.18,117.68
XDS_RS232_TX: R26.2 R181.1 U12.13 | length 830.5
  Bottom Layer w6: R181.1@720.59,806.08 R181.1@720.59,800.08 720.59,778.94 735.54,763.98 R26.2@735.54,743.81 735.54,586.07 966.86,354.75 966.86,224.67 997.07,194.46 U12.13@1101.47,194.46
XDS_SCL: R199.2 S5.3 U21.112 | length 1374.4
  Top Layer w6: S5.3@657.84,399.25 657.84,463.64 638.12,483.36 638.12,540.98 726.4,629.26 983.24,629.26 1064.02,710.04 1142.08,710.04 1158.31,726.26 1158.31,1042.9 1209.11,1093.7 1209.11,1158.5 1219.02,1168.42 v1(1265.56,1168.42) 1254.27,1179.7 1254.27,1198.63 R199.2@1254.21,1198.69
  Bottom Layer w6: v1(1265.56,1168.42) 1267.36,1168.42 1274.59,1161.19 U21.112@1341.36,1161.19
XDS_SDA: R197.2 S5.4 U21.111 | length 1548.1
  Top Layer w6: S5.4@607.84,399.25 607.84,540.36 710.66,643.19 802.79,643.19 823.18,663.58 823.18,715.84 797.63,741.39 797.63,835.18 830.44,867.99 1033.89,867.99 1141.94,976.04 1141.94,1062.41 1179.3,1099.77 1179.3,1152.66 1147.43,1184.53 1147.43,1214.62 1159.41,1226.61 1244.02,1226.61 1254.21,1236.8 R197.2@1254.21,1257.95 1274.83,1257.95 1286.23,1246.55 v1(1286.23,1245.87)
  Bottom Layer w6: v1(1286.23,1245.87) 1286.23,1194.2 1303.49,1176.93 U21.111@1341.36,1176.93
XDS_TCK: R122.2 U4.1 | length 622.9
  Top Layer w6: R122.2@862.23,926.97 875.17,926.97 919.68,971.48 1083.38,971.48 1124.54,1012.63 1124.54,1074.98 1138.41,1088.85 1138.41,1151.2 1094.18,1195.43 1045.34,1195.43 1024.89,1174.98 U4.1@1024.89,1134.55
XDS_TDI: R125.2 U4.4 | length 639.5
  Top Layer w6: R125.2@862.23,1043.38 862.23,1054.93 855.84,1061.32 820.42,1061.32 793.86,1034.76 793.86,1019.46 789.16,1014.76 772.04,1014.76 768.53,1018.27 768.53,1076.71 746.35,1098.88 704.61,1098.88 693.56,1109.93 693.56,1142.1 723.14,1171.68 962.44,1171.68 977.65,1156.48 U4.4@977.65,1136.51
XDS_TDO: R84.2 U4.8 U21.37 | length 789.3
  Top Layer w6: v1(590.23,958.36) 603.27,945.32 694.27,945.32 704.34,955.39 704.34,1055.99 712.66,1064.31 742.87,1064.31 751.46,1055.72 751.46,997.28 762.32,986.41 805.75,986.41 820.48,1001.14 841.89,1001.14 849.34,993.69 868.39,993.69 924.72,1050.02 924.72,1074.34 931.78,1081.4 U4.8@954.03,1081.4
  Bottom Layer w6: v1(590.23,958.36) 602.15,958.36 606.43,954.07 R84.2@606.43,931.82 663.31,931.82 703.7,972.21 U21.37@735.06,972.21
XDS_TMS: R124.2 U4.11 | length 231.1
  Top Layer w6: R124.2@862.23,956.57 897.02,991.36 987.97,991.36 1009.14,1012.54 U4.11@1009.14,1073.52
XDS_UARTA_RX: R24.1 R82.1 R118.1 R127.2 R147.1 U12.7 | length 5822.7
  Top Layer w6: v1(1177.69,2147.68) 1179.23,2147.68 1191.08,2135.83 R82.1@1203.42,2135.83
  L3_SIG1 w6: v1(935.12,303.31) 890.84,259.03 890.84,147.61 911,127.46 1094.71,127.46 1233.47,266.22 1233.47,450.82 1277.26,494.61 1639.75,494.61 1811.67,666.52 1811.67,1005.69 1871.7,1065.72 1871.7,1231.32 1829.5,1273.52 1829.5,1409.73 v1(1950.39,1530.62) 2063.76,1643.98 2063.76,1863.09 1990.47,1936.38 1846.19,1936.38 1774.67,2007.9 1651.64,2007.9 1572.28,1928.53 1526.87,1928.53 1451.24,2004.16 1451.24,2024.92 1306.43,2169.73 1245.38,2169.73 1223.32,2147.68 v1@1179.69,2147.68
  Bottom Layer w6: R118.1@248.36,1916.01 271.9,1916.01 297.09,1941.2 393.64,1941.2 420.09,1914.76 420.09,1888.79 448.91,1859.96 637.63,1859.96 777.63,1999.97 1014.15,1999.97 1162.08,2147.89 1179.48,2147.89 v1@1179.69,2147.68 ; R24.1@603.36,790.97 603.36,423.67 743.95,283.08 793.29,283.08 R127.2@799.15,277.22 813.46,277.22 819.45,271.23 U12.7@869.18,271.23 869.43,270.98 902.8,270.98 v1(935.12,303.31)
  Bottom Layer w8: v1(1950.39,1530.62) 1950.39,1557.99 R147.1@1957.66,1565.25
XDS_UARTA_RX_CAN_RX: R127.1 U12.6 U15.1 | length 2592.5
  Top Layer w6: U15.1@1218.18,2009.1 1218.18,1966.25 1229.25,1955.18 v1(1229.25,1955.01)
  L3_SIG1 w6: v1(937.02,262.63) 965.91,233.74 1030.92,233.74 1068.46,271.28 1068.46,502.48 1282.95,716.97 1485.24,716.97 1529.37,761.1 1529.37,1834.85 1470.43,1893.78 1312.19,1893.78 1250.96,1955.01 v1(1229.25,1955.01)
  Bottom Layer w6: R127.1@799.15,229.98 799.62,229.51 816.78,229.51 832.92,245.64 U12.6@869.18,245.64 920.28,245.64 937.02,262.37 v1(937.02,262.63)
XDS_UARTA_TX: R26.1 R77.1 R81.1 R128.2 R143.1 R190.1 U12.11 | length 6961.7
  Top Layer w6: v1(1253.39,1907.98) 1253.39,1907.71 1278.48,1882.61 1278.48,1825.64 1297.86,1806.27 R128.2@1327.79,1806.27 1329.72,1804.34 1349.53,1804.34 1356.85,1797.02 1356.85,1783.44 v1@1356.92,1783.37
  L6_SIG2 w6: v1(937.86,684.6) 957.62,664.83 1096.1,664.83 1185.06,753.79 1185.06,1056.91 1211.77,1083.63 1387.12,1083.63 1515.67,1212.17 1515.67,1286.76 1637.64,1408.73 1722.74,1408.73 1884.28,1570.27 2302.34,1570.27 2361.57,1629.49 2361.57,1793.61 2305.36,1849.82 v1(2083.77,1849.82) 2055.86,1849.82 1976.19,1770.15 1617.73,1770.15 1522.69,1675.11 1454.14,1675.11 1432.63,1696.62 1432.63,1830.71 1497.11,1895.19 1497.11,1925.23 1476.47,1945.87 1447.06,1945.87 1368.14,1866.94 1368.14,1796.75 1356.92,1785.53 v1(1356.92,1784.26) v1@1356.92,1783.37
  Bottom Layer w6: R77.1@248.36,1962.7 637.05,1962.7 708.47,2034.11 875.27,2034.11 990.46,2149.3 1122.79,2149.3 1139.73,2166.24 1189.41,2166.24 1199.69,2155.96 1199.69,2139.56 R81.1@1203.42,2135.83 1205.36,2133.89 1214.02,2133.89 1254.68,2093.23 1254.68,2066.9 1180.15,1992.37 1051.78,1992.37 969.49,1910.08 969.49,1821.98 1010.92,1780.55 1095.6,1780.55 1181.63,1866.58 1211.99,1866.58 v1(1253.39,1907.98) ; R26.1@782.79,743.81 797.21,743.81 823.13,717.89 823.13,651.02 841.73,632.43 909.07,632.43 937.61,660.97 v1@937.61,684.6 ; R190.1@937.61,751 v1@937.61,684.6 ; U12.11@1101.47,245.64 1028.75,245.64 1008.28,266.11 1008.28,290.99 980.01,319.26 980.01,642.44 v1(937.86,684.6) v1@937.61,684.6
  Bottom Layer w10: R143.1@1949.41,1817.59 1949.41,1839.52 1959.72,1849.82 v1(2083.77,1849.82)
XDS_UARTA_TX_CAN_TX: R128.1 U12.10 U15.23 | length 2169.3
  Top Layer w6: U15.23@1192.59,1780.76 1192.64,1780.71 1192.64,1748.66 1200.73,1740.57 1240.16,1740.57 1258.62,1759.03 R128.1@1327.79,1759.03 1332.92,1764.16 1456.47,1764.16 v1(1471.35,1779.03)
  L3_SIG1 w6: v1(1028.28,286.59) 1028.28,429.16 1047.68,448.55 1047.68,512.58 1300.89,765.79 1300.89,826.03 1428.64,953.78 1428.64,1190.91 1413.98,1205.57 1413.98,1388.48 1372.66,1429.79 1372.66,1532.59 1516.4,1676.32 1516.4,1733.98 v1(1471.35,1779.03)
  Bottom Layer w10: v1(1028.28,286.59) 1043.65,271.23 U12.10@1101.47,271.23
XDSET_1_DM: J5.2 U9.4 U21.93 | length 1542
  Top Layer w9.42: U9.4@2198.26,940.6 2199.46,941.8 2203.82,941.8 2204.25,942.24 2229.77,942.24 2230.77,943.23 2238.57,943.23 2246.47,935.33 v1(2248.38,935.33) 2250.29,935.33 2258.19,943.23 2290.76,943.23 2292.18,941.81 2314.98,941.81 J5.2@2318.14,938.64
  Bottom Layer w6: U21.93@1235.06,1456.46 1235.06,1432.33 1237.44,1429.96 1237.44,1411.62 1253.78,1395.28 1289.42,1395.28 1324.74,1430.61 1403.32,1430.61 1520.9,1313.02 1745.55,1313.02 1773.21,1285.36 1830.99,1285.36 1892.93,1223.43 2079.72,1223.43 2115.34,1187.81 2115.34,967.92 2137.32,945.94 2155.06,945.94 2238.5,945.94 2248.38,936.06 v1(2248.38,935.33)
XDSET_1_DP: J5.3 U9.5 U21.94 | length 1540.7
  Top Layer w9.42: U9.5@2198.26,960.29 2199.46,959.09 2203.82,959.09 2204.25,958.66 2222.97,958.66 2223.96,959.65 2238.57,959.65 2246.47,967.55 v1(2248.38,967.55) 2250.29,967.55 2258.19,959.65 2290.76,959.65 2292.18,961.07 2314.98,961.07 J5.3@2318.14,964.23
  Bottom Layer w6: U21.94@1250.81,1456.46 1250.81,1432.33 1248.44,1429.96 1248.44,1416.18 1258.33,1406.28 1284.86,1406.28 1320.18,1441.61 1407.87,1441.61 1525.46,1324.02 1750.11,1324.02 1777.77,1296.36 1835.55,1296.36 1897.48,1234.43 2084.28,1234.43 2126.34,1192.37 2126.34,972.47 2141.87,956.94 2168.86,956.94 2177.23,965.31 2185.04,965.31 2193.41,956.94 2199.41,956.94 2207.78,965.31 2215.59,965.31 2223.96,956.94 2243.79,956.94 2248.38,961.52 v1(2248.38,967.55)
XDSET_1_ID: J5.4 R170.2 U9.2 | length 1423.2
  Top Layer w6: v1(2166.67,1042.79) 2157.89,1034.01 2157.89,966.7 2164.02,960.57 2174.35,960.57 U9.2@2174.64,960.29 ; v1(2238.47,1014.57) 2263.22,989.82 J5.4@2318.14,989.82
  Bottom Layer w6: R170.2@1417.72,1568.73 1440.88,1568.73 1463.07,1546.54 1463.07,1503.5 1440.69,1481.12 1440.69,1435.17 1534.17,1341.69 1751.26,1341.69 1772.65,1320.29 1829.81,1320.29 1903.04,1247.06 2110.46,1247.06 2148.83,1208.69 2148.83,1060.62 v1(2166.67,1042.79) 2210.58,1042.79 2238.47,1014.89 v1(2238.47,1014.57)
XDSET_1_VBUS: R1.1 R169.2 R236.2 U9.6 | length 2299.3
  Top Layer w12: v1(2025.04,1041.75) 2025.04,1075.33 R1.1@2025.5,1075.79 2176.33,1075.79 2198.26,1053.86 U9.6@2198.26,979.97
  L3_SIG1 w15: v1(1439.87,1539.32) 1444.84,1539.32 1445.2,1538.96 1450.68,1538.96 1474.48,1515.16 1474.48,1237.48 1499.4,1212.56 1499.4,1178.73 1462.57,1141.9 1462.57,953.13 1405.45,896.01 1405.45,834.04 1441.01,798.48 v1(1441.01,798.37)
  Bottom Layer w15: R236.2@1351.75,754.25 1396.89,754.25 ; R169.2@1411.58,1531.41 1413.92,1533.75 1432.21,1533.75 1438.82,1540.36 v1(1439.87,1539.32) ; v1(1441.01,798.37) 1396.89,754.25 ; v1(2025.04,1041.75) 2025.04,860.78 1955.72,791.46 1955.72,666.77 1901.06,612.11 1693.8,612.11 1652.07,653.84 1497.3,653.84 1396.89,754.25
XTALM: C33.2 U1.B1 Y1.1 | length 269.4
  Top Layer w4: U1.B1@1307.85,2517.25 1308.96,2518.37 1312.95,2518.37 1323.02,2528.44 1362.69,2528.44 1400.24,2565.99 v1(1489.33,2565.99)
  Bottom Layer w4: Y1.1@1455.45,2575.13 1468.06,2587.74 C33.2@1494.18,2587.74 1489.33,2582.89 v1(1489.33,2565.99)
XTALP: C32.2 U1.D1 Y1.3 | length 296.7
  Top Layer w4: U1.D1@1268.48,2517.25 1272.05,2517.25 1295.1,2540.31 1308.77,2540.31 1314.5,2546.04 1348.19,2546.04 1392.38,2590.22 1392.38,2611.54 v1(1392.38,2658.99)
  Bottom Layer w4: v1(1392.38,2658.99) 1417.81,2658.99 C32.2@1418.47,2658.32 1418.47,2636.58 Y1.3@1400.33,2618.44
pads on no net: FID1.1 FID2.1 FID3.1 FID4.1 FID5.1 FID6.1 J6.14 J6.15 J6.16 J6.17 J6.19 J6.20 J6.21 J6.22 J6.23 J6.25 J6.27 J6.29 J6.31 J6.33 J6.35 J6.37 J6.39 J6.41 J6.43 J6.45 J6.47 J6.49 J6.MH1 J6.MH2 J8.3 J8.6 J8.8 J8.9 J8.10 J8.11 J8.12 J8.16 J9.3 J9.4 J9.5 J9.7 J9.8 J9.11 J9.15 J9.18 J9.20 LBL1.0 S4.4 U11.1 U11.2 U13.7 U13.9@1731.38,750.07 U13.9@1731.38,799.68 U14.9 U14.10 U14.11 U14.13 U14.14 U14.15 U21.2 U21.3 U21.4 U21.5 U21.6 U21.11 U21.12 U21.13 U21.14 U21.15 U21.18 U21.19 U21.20 U21.21 U21.22 U21.23 U21.24 U21.27 U21.29 U21.30 U21.31 U21.32 U21.41 U21.42 U21.43 U21.44 U21.45 U21.46 U21.49 U21.50 U21.53 U21.54 U21.56 U21.57 U21.65 U21.67 U21.71 U21.72 U21.73 U21.74 U21.75 U21.76 U21.77 U21.78 U21.81 U21.82 U21.83 U21.84 U21.85 U21.86 U21.91 U21.92 U21.97 U21.98 U21.99 U21.100 U21.102 U21.103 U21.104 U21.105 U21.106 U21.107 U21.108 U21.109 U21.110 U21.116 U21.117 U21.118 U21.119 U21.120 U21.121 U21.123 U21.124 U21.125 U21.126 U21.127 U21.128 U22.3 U23.3 U23.8

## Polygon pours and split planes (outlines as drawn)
no net on Bottom Solder (solid): 1190.78,2490.11 1186.73,2494.16 1186.67,2496.96 1184.25,2499.38 1162.67,2499.38 1160.05,2496.76 1160.05,2491.82 1157.13,2488.9 1089.76,2488.9 1076.7,2501.97 1076.7,2502.7 1045.76,2533.63 1045.76,2563.11 1046.65,2598.8 1031.59,2613.86 995.01,2613.86 883.86,2725.01 883.86,3159.47 884.14,3159.76 2454.83,3159.76 2454.83,2390.97 1384.95,2390.97 1348.96,2426.97 1303.21,2426.97 1303.21,2466.99 1285.35,2484.84 1280.08,2490.11
VCC_3V3 on L4_PWR1 "L4_SIGNAL 2-VCC_3V3" (solid, remove dead copper, pour order 45114): 0,3185.25 2480.32,3185.25 2480.32,0 0,0 0,3185.25
RADAR_3V3 on L4_PWR1 "L4_SIGNAL 2-RADAR_3V3" (solid, remove dead copper, pour order 45000): 1323.64,1913.83 1628.05,1913.83 1896.99,1644.89 1901.13,1644.89 2062.94,1806.7 1573.13,2296.51 963.39,2297.26 963.39,1991.5 1245.98,1991.5
GND on L4_PWR1 "Top Layer-GND 4" (solid, remove dead copper, pour order 45082): 1086.11,2483.08 1280.2,2483.08 1292.48,2470.81 1291.06,2469.39 1291.06,2422.65 1340.99,2372.72 1398.89,2372.72 2480.32,2372.72 2480.32,3195.22 796.65,3195.22 796.65,2772.55 1068.67,2500.53
RADAR_1V2 on L4_PWR1 "L4_SIGNAL 2-RADAR_1V2" (solid, remove dead copper, pour order 44778): 763.61,2468.6 794.23,2499.22 992.71,2499.22 1024.11,2468.6 1230.3,2468.6 1339.69,2359.22 1339.69,2311.44 943.44,2311.44 943.44,2177.25 763.61,2177.25
GND on L6_SIG2 "L6_SIGNAL 4-GND" (solid, remove dead copper, pour order 45136): 0,3185.25 2480.32,3185.25 2480.32,0 0,0
VCC_3V3 on L6_SIG2 "L6_SIGNAL 4-VCC_3V3" (solid, remove dead copper, pour order 44536): 1554.86,1874.18 1551.59,1870.91 1551.59,1814.5 1558.08,1808.01 1597.27,1808.01 1625.12,1835.86 1625.12,1850.18 1760.96,1850.18 1811.63,1900.86 1889.11,1900.86 1906.69,1883.28 1906.69,1833.75 1917.26,1823.18 1931.15,1823.18 1946.54,1838.58 1946.54,1903.78 1917.86,1932.45 1762.11,1932.45 1725.89,1896.23 1590.66,1896.23
VCC_3V3 on Bottom Layer "Bottom Layer-VCC_3V3" (solid, remove dead copper, pour order 45036): 1745.69,1691.47 1743.48,1689.27 1669.64,1689.27 1664.46,1694.45 1586.14,1772.78 1547.96,1772.78 1547.97,1883.14 1595.75,1883.14 1642.12,1836.77 1642.12,1811.01 1680.35,1772.78 1743.47,1772.78 1745.62,1770.63
GND on Bottom Layer "Top Layer-GND 4" (solid, remove dead copper, pour order 44948): 993.9,2616.28 1031.08,2616.43 1045.64,2601.88 1045.26,2538.24 1097.48,2486.01 1276.34,2486.01 1291.67,2470.67 1291.67,2430.42 1318.88,2403.2 1375.11,2403.2 1386.45,2391.73 2480.32,2391.73 2480.32,3193.66 869.82,3193.66 869.81,2738.9
VCC_3V3 on Bottom Layer "Bottom Layer-VCC_3V3 1" (solid, remove dead copper, pour order 45122): 217.22,2260.1 218.41,2261.29 218.41,2290.65 201.94,2307.13 156.1,2307.13 136.05,2287.07 136.05,2259.86 157.3,2238.61 157.3,2159.65 164.87,2152.08 186.55,2152.08 193.05,2158.58 193.05,2209.33 204.07,2220.35 211.83,2220.35 215.81,2224.32 215.81,2233.36
VCC_3V3 on Bottom Layer "Bottom Layer-VCC_3V3 2" (solid, remove dead copper, pour order 45120): 1243.96,1787.74 1253.63,1778.07 1282.26,1778.07 1287.83,1772.5 1294.89,1772.82 1298.07,1769.65 1297.99,1750.08 1257.36,1751.01 1249.49,1743.13 1249.49,1695.14 1307.5,1637.12 1327.31,1637.12 1336.7,1627.72 1336.7,1613.09 1322.81,1599.2 1305.08,1599.2 1305.08,1619.77 1283.76,1641.09 1280.63,1641.09 1237.41,1684.31 1209.76,1684.31 1197.18,1696.9 1197.18,1732.63 1205.61,1741.07 1205.61,1785.41 1207.95,1787.74
5V_IN on Bottom Layer "Bottom Layer-5V_IN 1" (solid, remove dead copper, pour order 45056): 450.98,2255.34 464.2,2242.12 568.29,2242.12 578.55,2231.86 625.92,2231.86 636,2241.94 636,2277.68 633.1,2280.57 507.46,2280.57 483.29,2304.74 483.29,2354.15 473.17,2364.27 340.08,2364.27 300.37,2364.27 300.37,2335.17 305.91,2329.63 305.91,2255.34 394.6,2255.34
REG_1V2 on Bottom Layer "Top Layer-REG_RF_1V2" (solid, remove dead copper, pour order 44856): 670.96,2355.2 513.57,2355.2 513.57,2293.06 570.9,2293.06 586.18,2308.35 777.89,2308.35 777.89,2454.31 670.96,2454.31
MCU_3V3 on Bottom Layer "Bottom Layer-MCU_3V3" (solid, remove dead copper, pour order 45060): 229.36,2264.91 227.29,2262.83 227.29,2228.03 239.24,2216.08 239.24,2183.69 252.64,2170.28 374.99,2170.28 381.62,2176.91 381.62,2216.41 366.58,2231.44 294.73,2231.44 275.36,2250.81 275.36,2262.27 273.07,2264.57
GND on Bottom Layer "Bottom Layer-GND 3" (solid, remove dead copper, pour order 45096): 1337.45,2284.63 1361.44,2260.64 1470.16,2260.64 1498.07,2232.72 1704.62,2231.94 1704.62,2297.97 1493.76,2297.97 1463.4,2328.33 1380.05,2328.33 1365.28,2343.11 1337.45,2343.11
GND on Bottom Layer "Bottom Layer-GND 7" (solid, remove dead copper, pour order 45044): 1067.86,2237.4 1067.86,2247.63 1089.97,2269.74 1089.97,2276 1094.87,2280.91 1094.85,2304.79 1072.93,2304.79 1064.98,2296.83 1030.95,2296.83 1030.95,2270.66 1020.24,2259.95 964.73,2259.95 957.45,2252.67 957.45,2219.99 969.17,2208.26 1038.72,2208.26
RADAR_1V2 on Bottom Layer "Bottom Layer-RADAR_1V2 1" (solid, remove dead copper, pour order 45038): 1197.17,2323.07 1197.17,2303.8 1193.24,2299.87 1131.11,2299.87 1112.4,2318.58 1070.67,2318.58 1062.07,2309.98 972.05,2309.98 926.13,2264.06 926.13,2229.36 912.78,2216.01 871.14,2216.01 859.4,2227.75 859.93,2228.29 859.93,2277.94 919.8,2337.81 1068.49,2337.81 1077.86,2347.18 1077.86,2363.4 1083.57,2369.11 1092.03,2369.11 1098.19,2362.94 1098.19,2342.28 1105.2,2335.27 1126.56,2335.27 1138.43,2323.4 1138.52,2323.5 1177.13,2323.5
RADAR_1P2_RF on Bottom Layer "Bottom Layer-RADAR_1P2_RF" (solid, remove dead copper, pour order 44970): 1006.84,2531.46 1006.84,2507.58 1049.76,2507.58 1073.82,2483.52 1086.95,2470.4 1086.95,2454.4 1082.74,2450.19 1067.97,2450.19 1065.69,2452.39 905.47,2452.39 905.47,2519.26 905.47,2557.01 879.95,2582.54 879.95,2643.05 832.79,2690.03 719.27,2690.03 664.79,2690.03 663.99,2750.29 843.76,2750.29 954.62,2639.44 954.62,2583.68
GND on Bottom Layer "Bottom Layer-GND 2" (solid, remove dead copper, pour order 45100): 639.65,2144.14 516.12,2144.14 501.93,2129.95 501.93,2048.17 596.11,2048.17 596.11,2090.41 608.97,2103.26 636.35,2103.26 642.31,2109.22 642.31,2140.89 641.94,2141.26
MCU_5V on Bottom Layer "Bottom Layer-MCU_5V" (solid, remove dead copper, pour order 45058): 653.14,2215.16 653.14,2283.51 714.86,2283.51 714.86,2154.27 502.73,2154.27 502.73,2215.16
NetC42_1 on Bottom Layer "Bottom Layer-NetC42_1" (solid, remove dead copper, pour order 44872): 1767.39,963.4 1797.71,933.08 1797.71,781.36 1776.28,781.36 1774.34,783.3 1774.34,835.99 1763.24,847.09 1763.24,918.68 1747.32,935.53 1652.26,935.53 1652.26,973.54 1707.81,973.54 1718.09,963.36
SW2 on Bottom Layer "Top Layer-SW2" (solid, remove dead copper, pour order 44850): 299.62,2395.72 299.82,2449.67 296.8,2452.69 285.3,2452.69 282.98,2455.02 282.98,2483.82 285.88,2486.72 337.92,2486.72 342.45,2482.19 342.45,2456.29 338.26,2452.11 317.94,2452.11 312.6,2446.77 312.6,2396.19
RADAR_3V3 on Bottom Layer "Bottom Layer-GND 6" (solid, remove dead copper, pour order 45080): 1808.22,1688.66 1907.28,1688.66 1907.28,1768.33 1808.22,1768.34
REG_OUT_1V2 on Bottom Layer "Top Layer-REG_OUT_3V3" (solid, remove dead copper, pour order 44852): 774.34,2621.55 477.96,2621.55 318.11,2621.55 282.72,2586.17 282.72,2496.83 658.74,2496.83 672.82,2482.75 774.03,2482.75
GND on Bottom Layer "Bottom Layer-GND 6" (solid, remove dead copper, pour order 45078): 1928.71,2224.32 2027.77,2224.32 2027.77,2303.12 1928.71,2303.12
RADAR_1V8 on Bottom Layer "Bottom Layer-RADAR_1V8 1" (solid, remove dead copper, pour order 45052): 1110.99,2430 1095.25,2414.26 1015.93,2414.26 1015.93,2438.23 1021.65,2443.95 1022.45,2444.75 1055.93,2444.75 1058.05,2442.63 1094.36,2442.63 1096.49,2444.75 1107,2444.75 1111.03,2440.72 1111.03,2437.38
GND on Bottom Layer "Bottom Layer-GND 8" (solid, remove dead copper, pour order 45042): 968.95,2403.94 927.16,2403.94 918.57,2412.46 891.86,2412.44 824.3,2412.44 820.41,2416.33 820.41,2435.89 820.41,2535.43 791.49,2564.35 791.49,2643.19 861.91,2643.19 861.91,2583.87 889.98,2555.8 889.93,2444.31 980.21,2444.31 981.87,2442.65 981.87,2416.87
GND on Bottom Layer "Bottom Layer-GND 6" (solid, remove dead copper, pour order 45040): 312.94,2763.28 246.05,2763.28 246.05,2666.29 312.94,2666.29
CB_REG_RF_1V2 on Bottom Layer "Bottom Layer-CB_REG_RF_1V2" (solid, remove dead copper, pour order 45020): 452.66,2860.35 452.28,2771.82 703.13,2771.82 703.13,2858.41 704.47,2860.35
GND on Bottom Layer "Top Layer-GND 6" (solid, remove dead copper, pour order 44858): 347.13,2374.35 346.36,2373.57 252.47,2373.57 235.65,2356.76 215.06,2356.76 210.21,2361.62 210.21,2377.88 219.64,2387.32 321.05,2387.32 321.05,2433.13 331.56,2443.65 359.6,2443.65 367.48,2451.53 367.48,2483.26 622.45,2483.26 653.53,2452.18 653.53,2374.35 516.75,2374.35
GND on Bottom Layer "Top Layer-GND 7" (solid, remove dead copper, pour order 44864): 881.4,2403.15 881.4,2319.21 817.15,2319.21 817.15,2403.15
REG_1V8 on Bottom Layer "Bottom Layer-GND 6" (solid, remove dead copper, pour order 45030): 1817.96,2118.89 1969.42,2118.89 1969.42,2198.57 1817.96,2198.57
CB_REG_1V8 on Bottom Layer "Bottom Layer-CB_REG_1V8" (solid, remove dead copper, pour order 45028): 1688.68,2122.3 1688.77,2199.37 1786.2,2296.8 1786.2,2373.6 1867.82,2373.6 1867.82,2220.86 1819.99,2220.86 1756.94,2157.8 1756.94,2122.3
REG_RF_1V2 on Bottom Layer "Top Layer-REG_1V2" (solid, remove dead copper, pour order 44854): 385.07,2673.16 329.09,2729.15 329.09,2864.6 404.55,2864.59 404.55,2784.11 483.37,2705.3 483.37,2635.63 385.07,2635.63
GND on Bottom Layer "Bottom Layer-GND 5" (solid, remove dead copper, pour order 44976): 734.2,2766.9 856.83,2766.9 856.83,2834.15 735.09,2834.15
GND on Bottom Layer "Bottom Layer-GND 6" (solid, remove dead copper, pour order 44974): 646.97,2633.08 646.97,2712.01 543.82,2712.01 543.82,2633.08
RADAR_1V8 on Bottom Layer "Bottom Layer-RADAR_1V8" (solid, remove dead copper, pour order 44892): 1365.28,2379.05 1362.97,2381.64 1348.71,2381.64 1340.18,2390.17 1309.58,2390.17 1305.76,2393.99 1305.76,2404.53 1282.83,2427.46 1257.18,2427.46 1257.18,2402.61 1270.57,2389.23 1277.91,2389.23 1292.38,2374.76 1309.7,2374.76 1331.03,2355.58 1376.24,2355.58 1385.46,2346.35 1465.13,2346.35 1500.24,2311.24 1767.65,2311.24 1767.65,2372.86 1574.56,2372.86 1568.41,2379
5V_IN on Bottom Layer "Bottom Layer-5V_IN" (solid, remove dead copper, pour order 44866): 1635.57,880.14 1635.57,983.42 1580.55,983.42 1580.55,880.14
GND on Bottom Layer "Bottom Layer-GND 4" (solid, remove dead copper, pour order 44977): 1020.25,2379.06 1018.77,2377.58 1018.77,2352.86 1012.59,2346.68 990.45,2346.68 990.45,2406.03 1020.23,2406.08 1086.49,2406.08 1088.32,2404.25 1091.48,2400.96 1091.48,2382.09 1092.3,2381.26 1090.07,2379.03 1036.74,2379.03
VCC_XDS_3V3 on Bottom Layer "Bottom Layer-VCC_XDS_3V3" (solid, remove dead copper, pour order 44878): 1912.22,671.04 1925.1,683.92 1925.02,683.92 1925.02,754.78 1805.49,754.78 1805.49,768.95 1775.18,769.17 1775.18,724.53 1781.18,718.53 1821.15,718.53 1832.72,706.96 1832.72,674.42 1836.1,671.04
